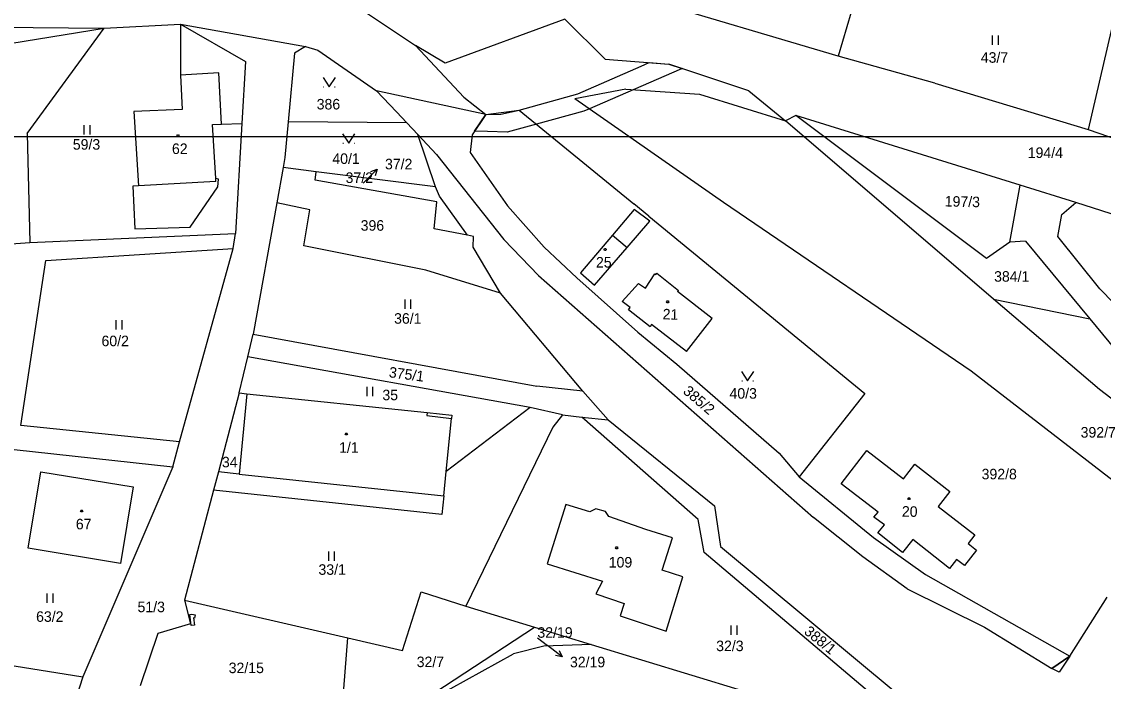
# Model space of a CAD drawing. Extents: x -811039 to -805820, y -1161436 to -1155864.
# Drawn here: x -806560.9 to -806386.2, y -1158088 to -1157981.5 of the extents above; entities that cross this region are included whole.
import ezdxf

# ---------------------------------------------------------------- set-up
doc = ezdxf.new("R2010")
doc.units = 0
for name, color, linetype in [('Default', 7, 'Continuous'), ('Hranice parcel', 7, 'Continuous'), ('ML1000', 7, 'Continuous'), ('Parcelní čísla', 7, 'Continuous'), ('Pop  PČ popisy', 7, 'Continuous'), ('Vnitřní kresba', 7, 'Continuous'), ('Věcná břemena k části', 7, 'Continuous'), ('Značky budov', 7, 'Continuous'), ('Značky kultur', 7, 'Continuous')]:
    doc.layers.add(name, color=color, linetype=linetype)

# ---------------------------------------------------------------- blocks, each defined once
blk = doc.blocks.new('306')
at = {"layer": 'Default'}
for p, q in [((-0.5, 1.5), (-0.5, 0)), ((0.5, 0), (0.5, 1.5))]:
    blk.add_line(p, q, dxfattribs=at)
blk = doc.blocks.new('314')
at = {"layer": 'Default'}
for p, q in [((-0.95, 0), (-0.85, 0)), ((0.85, 0), (0.95, 0))]:
    blk.add_line(p, q, dxfattribs=at)
blk.add_lwpolyline([(-1, 1.5), (0, 0), (1, 1.5)], dxfattribs=at)
blk = doc.blocks.new('10292')
at = {"layer": 'Default'}
blk.add_line((0, 3), (0, 0), dxfattribs=at)
blk.add_lwpolyline([(-0.5, 2), (0, 3), (0.5, 2)], dxfattribs=at)
blk = doc.blocks.new('402')
at = {"layer": 'Default'}
blk.add_lwpolyline([(0.09, 0.15), (0.18, 0), (0.09, -0.15), (-0.09, -0.15), (-0.18, 0), (-0.09, 0.15), (0.09, 0.15)], dxfattribs=at)

msp = doc.modelspace()

# ---------------------------------------------------------------- linework, layer by layer
at = {"layer": 'Hranice parcel'}
for p, q in [((-806515.35, -1157973.25), (-806497.28, -1157985.34)), ((-806424.9, -1157973.07), (-806429.06, -1157987.06)), ((-806383.1, -1157974.77), (-806388.68, -1157998.88)), ((-806429.06, -1157987.06), (-806462.21, -1157977.22)), ((-806473.17, -1157981.08), (-806492.48, -1157988.16)), ((-806473.17, -1157981.08), (-806466.66, -1157987.53)), ((-806593.91, -1157982.13), (-806547.55, -1157982.51)), ((-806570.5, -1157986.22), (-806547.55, -1157982.51)), ((-806559.98, -1157999.53), (-806547.55, -1157982.51)), ((-806547.55, -1157982.51), (-806535.26, -1157981.87)), ((-806535.26, -1157981.87), (-806524.76, -1157987.91)), ((-806535.26, -1157981.87), (-806535.24, -1157990.09)), ((-806535.26, -1157981.87), (-806515.08, -1157985.46)), ((-806515.08, -1157985.46), (-806516.85, -1157986.57)), ((-806515.08, -1157985.46), (-806513.04, -1157986.1)), ((-806513.04, -1157986.1), (-806503.58, -1157992.63)), ((-806497.28, -1157985.34), (-806489.51, -1157993.66)), ((-806492.48, -1157988.16), (-806497.28, -1157985.34)), ((-806524.76, -1157987.91), (-806525.33, -1157997.9)), ((-806516.85, -1157986.57), (-806517.87, -1157997.67)), ((-806466.66, -1157987.53), (-806456.36, -1157988.35)), ((-806413.41, -1157991.42), (-806429.06, -1157987.06)), ((-806443.47, -1157992.64), (-806456.36, -1157988.35)), ((-806535.24, -1157990.09), (-806534.96, -1157995.68)), ((-806413.41, -1157991.42), (-806388.68, -1157998.88)), ((-806503.58, -1157992.63), (-806500.35, -1157996.02)), ((-806485.92, -1157996.44), (-806503.58, -1157992.63)), ((-806463.35, -1157992.4), (-806471.54, -1157993.92)), ((-806463.35, -1157992.4), (-806451.44, -1157993.16)), ((-806451.44, -1157993.16), (-806437.53, -1157997.48)), ((-806443.47, -1157992.64), (-806437.53, -1157997.48)), ((-806489.51, -1157993.66), (-806485.92, -1157996.44)), ((-806447.58, -1158010.64), (-806471.54, -1157993.92)), ((-806534.96, -1157995.68), (-806542.76, -1157995.99)), ((-806542.76, -1157995.99), (-806542.05, -1158008)), ((-806498.69, -1157997.8), (-806500.35, -1157996.02)), ((-806485.92, -1157996.44), (-806488.17, -1157999.72)), ((-806485.92, -1157996.44), (-806480.54, -1157995.78)), ((-806480.54, -1157995.78), (-806462.02, -1158010.88)), ((-806435.86, -1157996.63), (-806437.53, -1157997.48)), ((-806399.64, -1158007.89), (-806435.86, -1157996.63)), ((-806405.11, -1158019.7), (-806435.86, -1157996.63)), ((-806530.07, -1157998.08), (-806528.61, -1157998)), ((-806529.55, -1158006.81), (-806530.07, -1157998.08)), ((-806528.61, -1157998), (-806525.33, -1157997.9)), ((-806525.33, -1157997.9), (-806526.35, -1158015.67)), ((-806517.87, -1157997.67), (-806518.4, -1158003.39)), ((-806498.69, -1157997.8), (-806517.87, -1157997.67)), ((-806496.9, -1157999.7), (-806498.69, -1157997.8)), ((-806403.97, -1158026.28), (-806437.53, -1157997.48)), ((-806559.98, -1157999.53), (-806559.56, -1158017.1)), ((-806493.88, -1158002.92), (-806496.9, -1157999.7)), ((-806494.05, -1158008.15), (-806496.9, -1157999.7)), ((-806488.17, -1157999.72), (-806488.47, -1158002.57)), ((-806388.68, -1157998.88), (-806381.62, -1158001.34)), ((-806518.4, -1158003.39), (-806518.69, -1158005.01)), ((-806493.88, -1158002.92), (-806483.05, -1158016.65)), ((-806488.47, -1158002.57), (-806482.44, -1158011.2)), ((-806518.69, -1158005.01), (-806519.71, -1158010.72)), ((-806513.35, -1158005.69), (-806518.69, -1158005.01)), ((-806513.52, -1158007.08), (-806513.35, -1158005.69)), ((-806494.05, -1158008.15), (-806513.35, -1158005.69)), ((-806529.1, -1158006.88), (-806529.55, -1158006.81)), ((-806529.21, -1158008.16), (-806529.1, -1158006.88)), ((-806493.83, -1158010.58), (-806513.52, -1158007.08)), ((-806542.05, -1158008), (-806542.93, -1158008.02)), ((-806542.93, -1158008.02), (-806542.62, -1158014.9)), ((-806533.68, -1158014.66), (-806529.21, -1158008.16)), ((-806493.41, -1158009.65), (-806494.05, -1158008.15)), ((-806401.34, -1158017.08), (-806399.64, -1158007.89)), ((-806390.69, -1158010.65), (-806399.64, -1158007.89)), ((-806519.71, -1158010.72), (-806523.5, -1158031.94)), ((-806514.38, -1158011.87), (-806519.71, -1158010.72)), ((-806494.26, -1158014.93), (-806493.83, -1158010.58)), ((-806488.91, -1158015.93), (-806493.41, -1158009.65)), ((-806459.64, -1158012.89), (-806462.02, -1158010.88)), ((-806407.54, -1158037.9), (-806447.58, -1158010.64)), ((-806392.94, -1158012.61), (-806390.69, -1158010.65)), ((-806376.12, -1158015.37), (-806390.69, -1158010.65)), ((-806515.31, -1158017.65), (-806514.38, -1158011.87)), ((-806482.44, -1158011.2), (-806476.53, -1158017.89)), ((-806462.01, -1158011.79), (-806465.47, -1158015.95)), ((-806459.45, -1158013.66), (-806462.01, -1158011.79)), ((-806393.59, -1158016.18), (-806392.94, -1158012.61)), ((-806463.14, -1158017.92), (-806459.45, -1158013.66)), ((-806459.64, -1158012.89), (-806424.73, -1158041.5)), ((-806559.56, -1158017.1), (-806526.35, -1158015.67)), ((-806542.62, -1158014.9), (-806533.68, -1158014.66)), ((-806526.74, -1158018.07), (-806526.35, -1158015.67)), ((-806488.91, -1158015.93), (-806494.26, -1158014.93)), ((-806487.91, -1158016.15), (-806488.91, -1158015.93)), ((-806487.98, -1158017.86), (-806487.91, -1158016.15)), ((-806465.47, -1158015.95), (-806470.67, -1158022.04)), ((-806386.8, -1158024.62), (-806393.59, -1158016.18)), ((-806600.28, -1158020.19), (-806559.56, -1158017.1)), ((-806495.62, -1158021.57), (-806515.31, -1158017.65)), ((-806483.56, -1158025.28), (-806487.98, -1158017.86)), ((-806483.05, -1158016.65), (-806477.41, -1158022.47)), ((-806476.53, -1158017.89), (-806471.26, -1158022.84)), ((-806468.38, -1158024.01), (-806463.14, -1158017.92)), ((-806401.34, -1158017.08), (-806405.11, -1158019.7)), ((-806398.79, -1158016.9), (-806401.34, -1158017.08)), ((-806398.79, -1158016.9), (-806388.41, -1158029.46)), ((-806556.99, -1158020.02), (-806526.74, -1158018.07)), ((-806535.38, -1158049.27), (-806526.74, -1158018.07)), ((-806561.02, -1158046.66), (-806556.99, -1158020.02)), ((-806483.56, -1158025.28), (-806495.62, -1158021.57)), ((-806477.41, -1158022.47), (-806433.02, -1158061.49)), ((-806471.26, -1158022.84), (-806461.38, -1158031.57)), ((-806470.67, -1158022.04), (-806468.38, -1158024.01)), ((-806460.18, -1158024.48), (-806458.64, -1158022.17)), ((-806458.64, -1158022.17), (-806458.51, -1158022.27)), ((-806458.51, -1158022.27), (-806458.31, -1158022.07)), ((-806458.31, -1158022.07), (-806454.85, -1158024.87)), ((-806463.9, -1158026.64), (-806461.29, -1158023.72)), ((-806461.29, -1158023.72), (-806460.18, -1158024.48)), ((-806454.85, -1158024.87), (-806454.96, -1158025.05)), ((-806379.13, -1158032.44), (-806386.8, -1158024.62)), ((-806470.28, -1158041.14), (-806483.56, -1158025.28)), ((-806462.62, -1158027.62), (-806463.9, -1158026.64)), ((-806449.4, -1158029.4), (-806454.96, -1158025.05)), ((-806386.86, -1158040.87), (-806403.97, -1158026.28)), ((-806403.97, -1158026.28), (-806388.41, -1158029.46)), ((-806462.9, -1158027.97), (-806462.62, -1158027.62)), ((-806459.38, -1158030.74), (-806462.9, -1158027.97)), ((-806453.55, -1158034.74), (-806449.4, -1158029.4)), ((-806388.41, -1158029.46), (-806380.92, -1158038.53)), ((-806524.37, -1158035.58), (-806523.5, -1158031.94)), ((-806523.5, -1158031.94), (-806477.72, -1158040.31)), ((-806461.38, -1158031.57), (-806455.07, -1158036.74)), ((-806459.17, -1158030.38), (-806459.38, -1158030.74)), ((-806453.55, -1158034.74), (-806459.17, -1158030.38)), ((-806525.75, -1158041.38), (-806524.37, -1158035.58)), ((-806478.78, -1158043.77), (-806524.37, -1158035.58)), ((-806455.07, -1158036.74), (-806438.57, -1158051.14)), ((-806365.29, -1158070.57), (-806407.54, -1158037.9)), ((-806470.28, -1158041.14), (-806477.72, -1158040.31)), ((-806525.75, -1158041.38), (-806529.12, -1158054.14)), ((-806524.55, -1158041.53), (-806525.79, -1158054.5)), ((-806525.75, -1158041.38), (-806524.55, -1158041.53)), ((-806524.55, -1158041.53), (-806495.43, -1158044.56)), ((-806470.28, -1158041.14), (-806466.19, -1158045.76)), ((-806424.73, -1158041.5), (-806435.36, -1158054.95)), ((-806373.03, -1158051.43), (-806386.86, -1158040.87)), ((-806478.78, -1158043.77), (-806492.33, -1158054.1)), ((-806473.53, -1158044.96), (-806478.78, -1158043.77)), ((-806495.43, -1158044.56), (-806491.42, -1158044.98)), ((-806492.33, -1158054.1), (-806491.47, -1158045.52)), ((-806491.42, -1158044.98), (-806491.47, -1158045.52)), ((-806473.53, -1158044.96), (-806475.11, -1158046.92)), ((-806473.53, -1158044.96), (-806470.44, -1158045.3)), ((-806470.44, -1158045.3), (-806466.19, -1158045.76)), ((-806451.67, -1158061.82), (-806470.44, -1158045.3)), ((-806466.19, -1158045.76), (-806449.03, -1158059.61)), ((-806535.38, -1158049.27), (-806561.02, -1158046.66)), ((-806475.11, -1158046.92), (-806489.16, -1158075.84)), ((-806536.5, -1158053.32), (-806535.38, -1158049.27)), ((-806562.08, -1158050.54), (-806536.5, -1158053.32)), ((-806438.57, -1158051.14), (-806435.36, -1158054.95)), ((-806428.54, -1158056.05), (-806424.44, -1158050.68)), ((-806424.44, -1158050.68), (-806418.49, -1158055.25)), ((-806418.49, -1158055.25), (-806416.65, -1158052.89)), ((-806416.65, -1158052.89), (-806411, -1158057.31)), ((-806559.82, -1158066.44), (-806557.77, -1158054.14)), ((-806557.77, -1158054.14), (-806542.9, -1158056.58)), ((-806536.5, -1158053.32), (-806551.02, -1158087.22)), ((-806529.12, -1158054.14), (-806529.89, -1158057.08)), ((-806525.79, -1158054.5), (-806529.12, -1158054.14)), ((-806492.73, -1158058.03), (-806492.33, -1158054.1)), ((-806435.36, -1158054.95), (-806423.34, -1158064.76)), ((-806422.57, -1158060.63), (-806428.54, -1158056.05)), ((-806542.9, -1158056.58), (-806544.93, -1158068.95)), ((-806529.89, -1158057.08), (-806534.57, -1158074.85)), ((-806493.03, -1158061.03), (-806529.89, -1158057.08)), ((-806492.73, -1158058.03), (-806493.03, -1158061.03)), ((-806411, -1158057.31), (-806412.87, -1158059.71)), ((-806473, -1158059.4), (-806476.02, -1158068.96)), ((-806469.12, -1158060.6), (-806473, -1158059.4)), ((-806449.03, -1158059.61), (-806448.04, -1158066.18)), ((-806412.87, -1158059.71), (-806406.95, -1158064.32)), ((-806468.17, -1158060.1), (-806469.12, -1158060.6)), ((-806466.63, -1158060.55), (-806468.17, -1158060.1)), ((-806466.1, -1158061.37), (-806466.63, -1158060.55)), ((-806460.11, -1158063.43), (-806466.1, -1158061.37)), ((-806425.05, -1158067.84), (-806433.02, -1158061.49)), ((-806423.26, -1158061.45), (-806422.57, -1158060.63)), ((-806421.58, -1158062.68), (-806423.26, -1158061.45)), ((-806450.67, -1158067.18), (-806451.67, -1158061.82)), ((-806422.65, -1158063.96), (-806421.58, -1158062.68)), ((-806455.77, -1158064.77), (-806460.11, -1158063.43)), ((-806457.45, -1158070.02), (-806455.77, -1158064.77)), ((-806423.34, -1158064.76), (-806414.94, -1158070.73)), ((-806418.65, -1158067.15), (-806422.65, -1158063.96)), ((-806416.97, -1158065.05), (-806418.65, -1158067.15)), ((-806411.06, -1158069.72), (-806416.97, -1158065.05)), ((-806406.95, -1158064.32), (-806408.03, -1158065.7)), ((-806544.93, -1158068.95), (-806559.82, -1158066.44)), ((-806448.04, -1158066.18), (-806419.5, -1158089.94)), ((-806406.7, -1158066.76), (-806408.66, -1158069.24)), ((-806408.03, -1158065.7), (-806406.7, -1158066.76)), ((-806421.5, -1158091.87), (-806450.67, -1158067.18)), ((-806417.91, -1158073.02), (-806425.05, -1158067.84)), ((-806409.96, -1158068.27), (-806411.06, -1158069.72)), ((-806408.66, -1158069.24), (-806409.96, -1158068.27)), ((-806476.02, -1158068.96), (-806467.11, -1158071.76)), ((-806454.13, -1158071.1), (-806457.45, -1158070.02)), ((-806467.11, -1158071.76), (-806468.17, -1158073.81)), ((-806456.84, -1158079.87), (-806454.13, -1158071.1)), ((-806414.94, -1158070.73), (-806391.65, -1158083.89)), ((-806499.42, -1158082.98), (-806496.39, -1158073.48)), ((-806496.39, -1158073.48), (-806489.16, -1158075.84)), ((-806468.17, -1158073.81), (-806463.61, -1158075.41)), ((-806417.91, -1158073.02), (-806405.43, -1158079.22)), ((-806534.57, -1158074.85), (-806533.65, -1158078.66)), ((-806534.57, -1158074.85), (-806508.21, -1158080.94)), ((-806463.61, -1158075.41), (-806464.26, -1158077.39)), ((-806391.65, -1158083.89), (-806385.61, -1158074.34)), ((-806489.16, -1158075.84), (-806478.06, -1158079.22)), ((-806533.65, -1158078.66), (-806538.91, -1158080.23)), ((-806464.26, -1158077.39), (-806456.84, -1158079.87)), ((-806538.91, -1158080.23), (-806541.73, -1158088.69)), ((-806502.01, -1158094.85), (-806478.06, -1158079.22)), ((-806478.06, -1158079.22), (-806468.91, -1158082)), ((-806405.43, -1158079.22), (-806394.55, -1158085.89)), ((-806509.31, -1158095.01), (-806508.21, -1158080.94)), ((-806508.21, -1158080.94), (-806499.42, -1158082.98)), ((-806476.57, -1158082.28), (-806481.45, -1158083.51)), ((-806468.91, -1158082), (-806476.57, -1158082.28)), ((-806468.91, -1158082), (-806424.62, -1158095.47)), ((-806502.01, -1158094.85), (-806481.45, -1158083.51)), ((-806391.65, -1158083.89), (-806394.55, -1158085.89)), ((-806566.96, -1158084.66), (-806551.02, -1158087.22)), ((-806551.02, -1158087.22), (-806553.63, -1158095.33))]:
    msp.add_line(p, q, dxfattribs=at)
at = {"layer": 'ML1000'}
msp.add_lwpolyline([(-806875, -1157000), (-806875, -1158000), (-806250, -1158000), (-806250, -1157000)], close=True, dxfattribs=at)
at = {"layer": 'Pop  PČ popisy'}
for p, q in [((-806505.72, -1158007.51), (-806505.61, -1158007.4)), ((-806477.62, -1158080.92), (-806475.98, -1158082.17))]:
    msp.add_line(p, q, dxfattribs=at)
at = {"layer": 'Vnitřní kresba'}
for p, q in [((-806529.04, -1157989.75), (-806535.24, -1157990.09)), ((-806528.61, -1157998), (-806529.04, -1157989.75)), ((-806529.55, -1158007.3), (-806542.05, -1158008)), ((-806529.55, -1158007.3), (-806529.55, -1158006.81)), ((-806465.47, -1158015.95), (-806463.14, -1158017.92)), ((-806495.43, -1158044.56), (-806495.48, -1158045.06)), ((-806495.48, -1158045.06), (-806491.47, -1158045.52)), ((-806525.79, -1158054.5), (-806492.73, -1158058.03))]:
    msp.add_line(p, q, dxfattribs=at)
at = {"layer": 'Věcná břemena k části'}
for points in [[(-806485.92, -1157996.44), (-806483.51, -1157996.4), (-806480.54, -1157995.78), (-806471.1, -1157993.11), (-806460.84, -1157988.65), (-806459.56, -1157988.09), (-806456.36, -1157988.35), (-806454.26, -1157989.05), (-806454.35, -1157989.09), (-806462.13, -1157992.48), (-806469.2, -1157995.56), (-806470.1, -1157995.95), (-806477.78, -1157998.03), (-806482.51, -1157999.32), (-806485.67, -1157999.21), (-806487.77, -1157999.14)], [(-806533.5, -1158078.94), (-806533.71, -1158077.15), (-806533.41, -1158077.12), (-806532.89, -1158077.24), (-806533, -1158077.73), (-806533.14, -1158077.7), (-806533, -1158078.88)], [(-806391.65, -1158083.89), (-806393.36, -1158086.46), (-806394.55, -1158085.89)]]:
    msp.add_lwpolyline(points, close=True, dxfattribs=at)

# ---------------------------------------------------------------- block references
at = {"layer": 'Pop  PČ popisy'}
for p, rotation in [((-806505.61, -1158007.4), -45.789945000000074), ((-806475.98, -1158082.17), -127.32183900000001)]:
    msp.add_blockref('10292', p, dxfattribs=dict(at, rotation=rotation))
at = {"layer": 'Značky budov'}
for p in [(-806535.66, -1157999.91), (-806466.67, -1158018.26), (-806456.56, -1158026.7), (-806508.46, -1158048.03), (-806417.59, -1158058.46), (-806551.2, -1158060.45), (-806464.81, -1158066.4)]:
    msp.add_blockref('402', p, dxfattribs=at)
at = {"layer": 'Značky kultur'}
for name, p in [('306', (-806403.65, -1157985.22)), ('314', (-806511.22, -1157991.99)), ('306', (-806550.34, -1157999.7)), ('314', (-806508.07, -1158001.1)), ('306', (-806498.54, -1158027.84)), ('306', (-806545.16, -1158031.16)), ('314', (-806443.66, -1158039.45)), ('306', (-806504.66, -1158041.91)), ('306', (-806510.86, -1158068.52)), ('306', (-806556.32, -1158075.27)), ('306', (-806445.87, -1158080.46))]:
    msp.add_blockref(name, p, dxfattribs=at)

# ---------------------------------------------------------------- texts
at = {"layer": 'Parcelní čísla'}
for s, p in [('43/7', (-806406.01, -1157988.11)), ('386', (-806513.25, -1157995.65)), ('59/3', (-806552.63, -1158002.14)), ('62', (-806536.62, -1158002.84)), ('194/4', (-806398.43, -1158003.48)), ('40/1', (-806510.72, -1158004.44)), ('37/2', (-806502.22, -1158005.31)), ('37/2', (-806508.58, -1158007.51)), ('396', (-806506.15, -1158015.22)), ('25', (-806468.15, -1158021.16)), ('384/1', (-806403.86, -1158023.45)), ('36/1', (-806500.75, -1158030.23)), ('60/2', (-806548, -1158033.86)), ('40/3', (-806446.59, -1158042.33)), ('35', (-806502.64, -1158042.58)), ('392/7', (-806389.89, -1158048.61)), ('1/1', (-806509.63, -1158051.06)), ('34', (-806528.55, -1158053.41)), ('392/8', (-806405.88, -1158055.35)), ('67', (-806552.14, -1158063.42)), ('109', (-806466.09, -1158069.58)), ('33/1', (-806512.96, -1158070.76)), ('51/3', (-806542.18, -1158076.79)), ('63/2', (-806558.56, -1158078.35)), ('32/19', (-806477.61, -1158080.92)), ('32/3', (-806448.74, -1158083.08)), ('32/7', (-806497.1, -1158085.66)), ('32/19', (-806472.35, -1158085.69)), ('32/15', (-806527.46, -1158086.63))]:
    msp.add_text(s, height=1.7, dxfattribs=at).set_placement(p)
for s, rotation, p in [('197/3', 358.614, (-806411.85, -1158011.3)), ('21', 357.755, (-806457.41, -1158029.51)), ('375/1', 352.541, (-806501.66, -1158038.86)), ('385/2', 319.424, (-806454.22, -1158041.34)), ('20', 358.786, (-806418.77, -1158061.36)), ('388/1', 321.028, (-806434.68, -1158080.16))]:
    msp.add_text(s, height=1.7, rotation=rotation, dxfattribs=at).set_placement(p)

doc.saveas('drawing.dxf')
